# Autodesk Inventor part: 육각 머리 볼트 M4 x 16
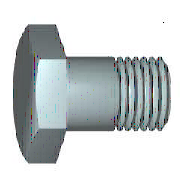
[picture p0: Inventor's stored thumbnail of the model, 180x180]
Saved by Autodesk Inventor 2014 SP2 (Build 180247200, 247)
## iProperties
IsCustomPart: 0
Created: 2012-02
Part Number: 육각 머리 볼트 M4 x 16
Material: 강철, 연강
Description: 6각 머리 볼트 및 6각 머리 나사
Document SubType Name: Modeling
Standard: KS B 1002
Designer: mduedu
Standards Organization: KS
Language: ko-KR
Size Designation: A + B M4 x 16
Categories: <MemberInstance><Categories><Category DisplayName="조임쇠" InternalName="e4da775c-781d-43d5-af7c-5136215cf5a6" Mnemonic="FSTN"><Category DisplayName="볼트" InternalN
Density: 7.86 g/cm^3
Appearance: 강철
Mass: 2.45486 g
Surface Area: 3.4613 cm^2
Volume: 0.312323 cm^3
Author: mduedu
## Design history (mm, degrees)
sketch "스케치1"
  geometry: L1 (0, 2.94)-(0, 2); L2 (2.1, 2)-(16, 2); L3 (16, 2)-(16, 0); L4 (16, 0)-(-0.4, 0); L5 (-3.68, 0)-(19.28, 0) reference; L6 (-0.4, 0)-(-0.4, 2.94); L7 (-0.4, 2.94)-(0, 2.94); L8 (2.1, 2)-(1.67, 2); L9 (1.67, 2)-(0, 2); L10 (0, -0.588)-(0, 3.528) reference
  constraints: 16 end point, 2 collinear, 2 perpendicular, 1 parallel
  dimensions: "d0" = 16 distance between parallel lines of L3 L1 (= NLG); "d1" = 13.9 distance from line of L2.start L3 (= GEL); "d2" = 4 diameter of L2 L4 (= GD); "d9" = 0.4001 distance between parallel lines of L6 L1 (computed from SD); "d10" = 5.88 diameter of L7 L4 (= SD2); "d13" = 0.42952 distance of L2.start L8.end (computed from GAL); "d14" = 4 diameter of L9 L4 (= BDM)
revolve "본체" sketch "스케치1" stored, may be unused: angle "d12" = 90 deg
sketch "스케치2"
  geometry: L1 (0, 4.041)-(3.5, 2.021); L2 (3.5, 2.021)-(3.5, -2.021); L3 (3.5, -2.021)-(0, -4.041); L4 (0, -4.041)-(-3.5, -2.021); L5 (-3.5, -2.021)-(-3.5, 2.021); L6 (-3.5, 2.021)-(0, 4.041); 2 further points
  constraints: 12 end point, 1 coincident, 1 vertical, 11 other
  dimensions: "d11" = 7 distance between parallel lines of L5 L2 (= SW)
extrude "머리" join sketch "스케치2" distance "d3" = 2.4 (= KOH - SD); taper "d4" = 0 deg
sketch "스케치4"
  geometry: L1 (-2.8, 3.5)-(-2.8, 4.041); L2 (-2.8, 4.041)-(-2.487, 4.041); L3 (-2.487, 4.041)-(-2.8, 3.5); L4 (-3.28, 0)-(0.08, 0) reference; L5 (-0.4, 4.041)-(-2.8, 4.041) reference; L6 (-2.8, 2.021)-(-2.8, 4.041) reference
  constraints: 6 end point, 2 collinear, 1 perpendicular, 1 vertical
  dimensions: "d5" = 30 deg angle of L3 L1 (= ANG1); "d19" = 7 diameter of L1.start L4 (= SW0)
revolve "모따기1" sketch "스케치4" stored, may be unused: angle "d21" = 90 deg
workplane "Work Plane1"
body "Solid1"
feature "스레드" dims "d15" = 13.9 (= GEL), "d16" = 0
chamfer "모따기2" distance "d6" = 0.42941 (= -0.5 x SPD + 0.5 x GD); stored, may be unused: second distance "d7" = 0.42952 (computed from GUL), angle "d55" = 45 deg
other parameters: "NLG" = 16 [user parameter; used in 1 equation term], "GD" = 4 (= NND) [user parameter; used in 2 equation terms], "BDM" = 4 (= NND) [user parameter; used in 1 equation term], "KOH" = 2.8 [user parameter; used in 1 equation term], "GEL" = 13.9 [user parameter; used in 2 equation terms], "SW" = 7 [user parameter; used in 3 equation terms], "SW0" = 7 (= SW) [user parameter; used in 1 equation term], "SPD" = 3.14117 (= NND - 1.2269 x PTC) [user parameter; used in 1 equation term], "SD2" = 5.88 (= SDH) [user parameter; used in 1 equation term], "SD" = 0.4 [user parameter; used in 2 equation terms], "ANG1" = 30 deg [user parameter; used in 1 equation term], "GAL" = 0.42941 (= 0.61345 x PTC) [user parameter; used in 1 equation term], "GUL" = 0.42941 (= 0.61345 x PTC) [user parameter; used in 1 equation term], "d8" = 0, "RR" = 0.2 [user parameter], "d57" = 0, "d58" = 0, "TPU" = 14.28571 (computed from PTC) [user parameter], "GD1" = 3.14117 (= THREADDIA - 1.2269 x PTC) [user parameter], "THREADDIA" = 4 [user parameter; used in 1 equation term], "SDH" = 5.88 [user parameter; used in 1 equation term], "SDHG" = 2.1 [user parameter], "TOA" = 30 deg [user parameter], "PTC" = 0.7 [user parameter; used in 5 equation terms], "NND" = 4 [user parameter; used in 3 equation terms], "E0" = 8.085 (= 1.155 x SW) [user parameter]
